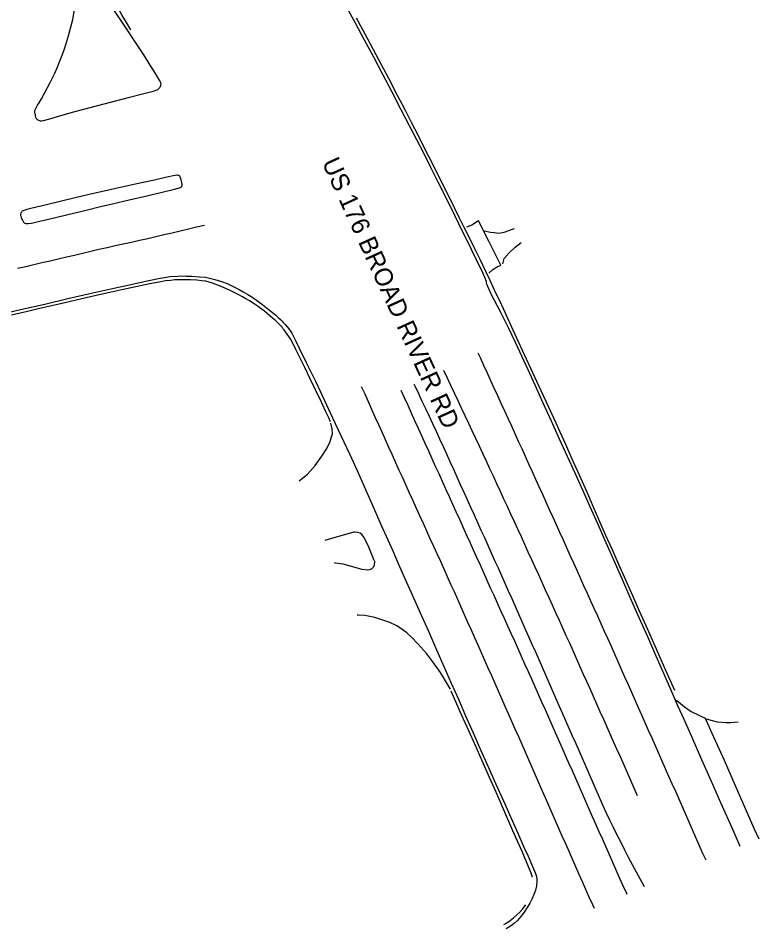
# Model space of a CAD drawing. Extents: x 1970211 to 1973046, y 801032 to 804001.
# Drawn here: x 1972824 to 1973045.8, y 801032.5 to 801305.3 of the extents above; entities that cross this region are included whole.
import ezdxf

# ---------------------------------------------------------------- set-up
doc = ezdxf.new("R2010")
doc.units = 0
for name, color, linetype in [('RD_EX_Conc', 7, 'Continuous'), ('RD_EX_Road', 7, 'Continuous'), ('RD_EX_Road_Paint', 7, 'Continuous'), ('RD_TX_RoadID', 7, 'Continuous')]:
    doc.layers.add(name, color=color, linetype=linetype)

msp = doc.modelspace()

# ---------------------------------------------------------------- linework, layer by layer
at = {"layer": 'RD_EX_Conc'}
for points in [[(1972851.73, 801309.15), (1972855.08, 801304.1), (1972859.53, 801297.36), (1972861.33, 801294.61), (1972862.52, 801292.76), (1972863.49, 801291.24), (1972864.56, 801289.55), (1972865.7, 801287.75), (1972866.4, 801286.57), (1972866.56, 801286.25), (1972866.63, 801286.04), (1972866.68, 801285.83), (1972866.71, 801285.63), (1972866.71, 801285.43), (1972866.69, 801285.26), (1972866.66, 801285.09), (1972866.62, 801284.95), (1972866.56, 801284.83), (1972866.41, 801284.59), (1972866.2, 801284.3), (1972865.99, 801284.03), (1972865.8, 801283.83), (1972865.55, 801283.71), (1972864.07, 801283.29), (1972861.3, 801282.59), (1972857.37, 801281.58), (1972852.4, 801280.28), (1972846.95, 801278.85), (1972841.32, 801277.37), (1972836.75, 801276.07), (1972833.45, 801275.04), (1972831.5, 801274.52), (1972831.03, 801274.46), (1972830.74, 801274.48), (1972830.48, 801274.54), (1972830.24, 801274.63), (1972830.03, 801274.74), (1972829.85, 801274.87), (1972829.69, 801275.01), (1972829.57, 801275.14), (1972829.48, 801275.27), (1972829.42, 801275.4), (1972829.36, 801275.54), (1972829.32, 801275.7), (1972829.27, 801276.02), (1972829.21, 801276.33), (1972829.13, 801276.63), (1972829.06, 801276.91), (1972829.01, 801277.17), (1972829.01, 801277.31), (1972829.03, 801277.47), (1972829.12, 801277.82), (1972829.29, 801278.23), (1972829.54, 801278.7), (1972829.87, 801279.26), (1972830.31, 801279.99), (1972831.01, 801281.21), (1972831.96, 801282.9), (1972832.85, 801284.53), (1972833.63, 801286.01), (1972834.34, 801287.42), (1972834.98, 801288.81), (1972835.68, 801290.43), (1972836.45, 801292.29), (1972837.19, 801294.2), (1972837.89, 801296.13), (1972838.53, 801298.05), (1972839.12, 801300.01), (1972839.73, 801302.29), (1972840.36, 801304.92), (1972840.91, 801307.84)], [(1972925.23, 801305.44), (1972927.14, 801301.93), (1972929.44, 801297.66), (1972932.05, 801292.76), (1972934.89, 801287.37), (1972937.58, 801282.21), (1972939.78, 801277.98), (1972941.77, 801274.15), (1972943.81, 801270.17), (1972945.86, 801266.13), (1972947.88, 801262.1), (1972950.01, 801257.82), (1972952.4, 801253.05), (1972954.59, 801248.65), (1972956.14, 801245.51), (1972957.44, 801242.87), (1972958.87, 801240), (1972960.49, 801236.72), (1972962.36, 801232.88), (1972964.09, 801229.31), (1972965.24, 801226.81), (1972966.14, 801224.84), (1972967.1, 801222.83), (1972968.13, 801220.69), (1972969.26, 801218.32), (1972970.7, 801215.22), (1972972.68, 801210.9), (1972975, 801205.83), (1972977.44, 801200.5), (1972979.84, 801195.28), (1972982.02, 801190.58), (1972983.81, 801186.72), (1972985.05, 801184.04), (1972986.24, 801181.41), (1972987.91, 801177.71), (1972989.89, 801173.28), (1972992.03, 801168.46), (1972994.2, 801163.57), (1972996.24, 801158.92), (1972998.17, 801154.53), (1972999.97, 801150.46), (1973001.81, 801146.32), (1973003.83, 801141.75), (1973005.93, 801137.01), (1973008, 801132.34), (1973010.02, 801127.77), (1973011.99, 801123.36), (1973015.1, 801116.34), (1973017.53, 801110.83), (1973020.55, 801103.98)], [(1972964.96, 801228.88), (1972966.17, 801230.04), (1972967.52, 801230.85), (1972968.61, 801231.33), (1972965.09, 801238.28), (1972961.92, 801244.63), (1972959.86, 801243.35), (1972958.28, 801242.72)], [(1972917.54, 801184.34), (1972917.02, 801185.62), (1972916.12, 801187.58), (1972914.84, 801190.28), (1972913.17, 801193.79), (1972911.41, 801197.47), (1972909.88, 801200.65), (1972908.5, 801203.47), (1972907.22, 801206.07), (1972906.18, 801208.11), (1972905.55, 801209.25), (1972905.09, 801209.95), (1972904.59, 801210.66), (1972904.1, 801211.33), (1972903.67, 801211.92), (1972903.32, 801212.39), (1972903.07, 801212.72), (1972902.78, 801213.06), (1972902.29, 801213.56), (1972901.66, 801214.17), (1972900.97, 801214.8), (1972900.23, 801215.47), (1972899.43, 801216.17), (1972898.61, 801216.88), (1972897.77, 801217.55), (1972896.82, 801218.26), (1972895.65, 801219.09), (1972894.41, 801219.92), (1972893.28, 801220.62), (1972892.21, 801221.24), (1972891.18, 801221.8), (1972890.08, 801222.39), (1972888.76, 801223.09), (1972887.3, 801223.83), (1972885.77, 801224.52), (1972884.35, 801225.12), (1972883.23, 801225.58), (1972882.26, 801225.95), (1972881.28, 801226.26), (1972880.23, 801226.51), (1972879.03, 801226.68), (1972877.53, 801226.8), (1972875.6, 801226.88), (1972873.67, 801226.93), (1972872.18, 801226.93), (1972870.92, 801226.88), (1972869.62, 801226.78), (1972868.13, 801226.59), (1972866.26, 801226.28), (1972863.48, 801225.73), (1972859.28, 801224.85), (1972855.11, 801223.95), (1972852.42, 801223.36), (1972850.09, 801222.85), (1972847.03, 801222.16), (1972843.06, 801221.25), (1972838.03, 801220.07), (1972833.25, 801218.94), (1972830.07, 801218.2), (1972826.86, 801217.47), (1972822.03, 801216.35)], [(1972930.66, 801142.87), (1972928.8, 801147.29), (1972927.6, 801149.87), (1972927.03, 801150.51), (1972926.41, 801151), (1972925.71, 801151.26), (1972924.94, 801151.32), (1972924.41, 801151.3), (1972923.83, 801151.16), (1972917.82, 801149.41), (1972915.89, 801148.87)], [(1972930.66, 801142.87), (1972930.7, 801142.53), (1972930.68, 801141.45), (1972930.36, 801140.77), (1972929.93, 801140.37), (1972929.29, 801140.06), (1972928.76, 801139.98), (1972927.02, 801140.09), (1972923.88, 801141), (1972921.36, 801141.7), (1972919.04, 801142.08), (1972918.81, 801142.1)], [(1972978.09, 801047.97), (1972977.68, 801049.15), (1972976.68, 801051.54), (1972974.92, 801055.61), (1972972.22, 801061.83), (1972969.37, 801068.37), (1972967.16, 801073.38), (1972965.18, 801077.86), (1972962.99, 801082.79), (1972960.86, 801087.61), (1972959.02, 801091.76), (1972956.84, 801096.64), (1972953.69, 801103.64)], [(1973021.14, 801101.03), (1973023.63, 801099), (1973025.59, 801097.63), (1973027.89, 801096.47), (1973029.73, 801095.56), (1973031.76, 801091.1), (1973035.42, 801083.01), (1973039.74, 801073.17), (1973044.37, 801062.68), (1973045.83, 801059.46)], [(1972969.51, 801033.79), (1972970.38, 801034.28), (1972971.39, 801034.98), (1972972.42, 801035.8), (1972973.4, 801036.66), (1972974.22, 801037.46), (1972975.05, 801038.39), (1972976.04, 801039.65)]]:
    msp.add_lwpolyline(points, dxfattribs=at)
msp.add_lwpolyline([(1972852.24, 801249.71), (1972853.85, 801250.08), (1972857.25, 801250.87), (1972862.56, 801252.11), (1972867.12, 801253.18), (1972870.46, 801253.97), (1972872.3, 801254.45), (1972872.65, 801254.58), (1972872.79, 801254.67), (1972872.91, 801254.76), (1972873, 801254.86), (1972873.06, 801254.97), (1972873.14, 801255.19), (1972873.18, 801255.41), (1972873.18, 801255.56), (1972873.08, 801256.09), (1972872.88, 801256.86), (1972872.69, 801257.46), (1972872.53, 801257.83), (1972872.44, 801257.96), (1972872.35, 801258.06), (1972872.25, 801258.13), (1972872.14, 801258.18), (1972872.01, 801258.22), (1972871.71, 801258.27), (1972871.52, 801258.28), (1972871.07, 801258.23), (1972870.47, 801258.11), (1972869.58, 801257.9), (1972868.16, 801257.57), (1972864.85, 801256.83), (1972859.54, 801255.66), (1972852.91, 801254.17), (1972845.32, 801252.45), (1972838.24, 801250.8), (1972832.12, 801249.35), (1972828.27, 801248.43), (1972826.67, 801248.04), (1972825.77, 801247.74), (1972825.49, 801247.6), (1972825.28, 801247.46), (1972825.11, 801247.29), (1972824.96, 801247.1), (1972824.85, 801246.89), (1972824.78, 801246.67), (1972824.75, 801246.45), (1972824.75, 801246.23), (1972824.8, 801246.01), (1972824.95, 801245.56), (1972825.14, 801245.07), (1972825.38, 801244.6), (1972825.67, 801244.2), (1972825.84, 801244.04), (1972826.06, 801243.91), (1972826.32, 801243.83), (1972826.61, 801243.78), (1972826.98, 801243.78), (1972827.98, 801243.92), (1972829.58, 801244.29), (1972833.12, 801245.13), (1972838.54, 801246.43), (1972844.04, 801247.75), (1972849.08, 801248.96)], close=True, dxfattribs=at)
at = {"layer": 'RD_EX_Road'}
for points in [[(1973040.29, 801057.1), (1973038.11, 801062), (1973034.47, 801070.23), (1973031.65, 801076.66), (1973028.8, 801083.16), (1973025.9, 801089.79), (1973023.51, 801095.16), (1973021.61, 801099.34), (1973019.45, 801104.21), (1973016.97, 801109.86), (1973014.68, 801115.1), (1973012.57, 801119.94), (1973010.12, 801125.5), (1973007.33, 801131.78), (1973004.78, 801137.56), (1973002.5, 801142.76), (1973000.16, 801148.08), (1972997.72, 801153.58), (1972995.36, 801158.88), (1972993.1, 801163.94), (1972990.83, 801168.97), (1972988.54, 801174.03), (1972986.17, 801179.23), (1972983.73, 801184.58), (1972981.28, 801189.98), (1972978.87, 801195.32), (1972976.74, 801200.01), (1972974.89, 801204.06), (1972972.98, 801208.12), (1972970.93, 801212.36), (1972968.44, 801217.31), (1972965.71, 801222.62), (1972964.36, 801225.59), (1972964.3, 801226.03), (1972964.28, 801226.4), (1972963.3, 801228.8), (1972961.29, 801232.96), (1972959.8, 801236.02), (1972958.86, 801237.93), (1972957.24, 801241.24), (1972954.85, 801246.16), (1972952.33, 801251.25), (1972949.83, 801256.23), (1972947.54, 801260.76), (1972945.47, 801264.86), (1972943.38, 801268.91), (1972941.2, 801273.08), (1972938.74, 801277.83), (1972936.01, 801283.15), (1972933.26, 801288.43), (1972930.53, 801293.61), (1972927.77, 801298.77), (1972925.02, 801303.85), (1972922.58, 801308.35)], [(1972963.61, 801241.59), (1972965.52, 801241.26), (1972966.63, 801241.14), (1972968.02, 801240.96), (1972969.61, 801241.25), (1972972.06, 801242.13), (1972972.64, 801242.32)], [(1972969.13, 801231.69), (1972969.61, 801233.37), (1972971.07, 801234.97), (1972972.85, 801236.76), (1972974.62, 801238.09)], [(1972817.17, 801216.28), (1972824.76, 801218), (1972832.01, 801219.68), (1972838.92, 801221.29), (1972845.49, 801222.83), (1972851.79, 801224.27), (1972857.73, 801225.58), (1972862.67, 801226.65), (1972866.54, 801227.46), (1972869.56, 801227.92), (1972871.8, 801228.06), (1972873.34, 801228.09), (1972874.37, 801228.06), (1972876.02, 801227.98), (1972878.31, 801227.86), (1972880.11, 801227.69), (1972881.37, 801227.47), (1972882.95, 801227.06), (1972884.9, 801226.47), (1972886.62, 801225.82), (1972888.02, 801225.15), (1972889.2, 801224.55), (1972890.23, 801224.01), (1972891.44, 801223.36), (1972892.85, 801222.57), (1972894.3, 801221.64), (1972895.78, 801220.56), (1972897.3, 801219.42), (1972898.85, 801218.24), (1972900.15, 801217.19), (1972901.18, 801216.3), (1972901.99, 801215.58), (1972902.6, 801215.02), (1972903.06, 801214.56), (1972903.42, 801214.15), (1972903.97, 801213.55), (1972904.7, 801212.74), (1972905.36, 801211.89), (1972905.96, 801210.92), (1972906.86, 801209.19), (1972908.18, 801206.48), (1972910.3, 801202.13), (1972913.14, 801196.32), (1972915.8, 801190.75), (1972918.19, 801185.61), (1972920.66, 801180.3), (1972923.21, 801174.83), (1972925.53, 801169.77), (1972927.63, 801165.05), (1972930.03, 801159.62), (1972932.68, 801153.61), (1972934.73, 801148.98), (1972936.19, 801145.73), (1972937.85, 801141.98), (1972939.85, 801137.48), (1972942.05, 801132.52), (1972944.42, 801127.18), (1972946.87, 801121.66), (1972949.34, 801116.06), (1972951.64, 801110.87), (1972953.75, 801106.09), (1972955.87, 801101.25), (1972958.04, 801096.28), (1972960.3, 801091.16), (1972962.63, 801085.92), (1972964.9, 801080.79), (1972967.1, 801075.8), (1972969.33, 801070.79), (1972971.55, 801065.8), (1972973.64, 801061.11), (1972975.5, 801056.94), (1972976.73, 801054.21), (1972977.36, 801052.83), (1972978.08, 801051.17), (1972978.93, 801049.1), (1972979.21, 801048.18), (1972979.36, 801047.37), (1972979.39, 801046.67), (1972979.25, 801045.39), (1972978.95, 801044.1), (1972978.5, 801042.81), (1972977.93, 801041.52), (1972977.23, 801040.2), (1972976.46, 801038.83), (1972975.57, 801037.46), (1972974.57, 801036.15), (1972973.57, 801035.02), (1972972.71, 801034.17), (1972971.81, 801033.47), (1972970.71, 801032.79), (1972970.14, 801032.49)], [(1972908.16, 801166.74), (1972910.63, 801168.7), (1972913.02, 801171.31), (1972915.01, 801174.12), (1972916.31, 801176.08), (1972917.34, 801178.17), (1972918.15, 801180.88), (1972918.11, 801182.25), (1972917.69, 801184.01)], [(1972953.53, 801104.33), (1972950.52, 801109.27), (1972948.22, 801112.5), (1972946.39, 801114.85), (1972943.75, 801117.88), (1972941.8, 801119.89), (1972940.38, 801121.12), (1972939.34, 801121.96), (1972937.42, 801123.25), (1972935.36, 801124.21), (1972933.26, 801124.99), (1972930.85, 801125.71), (1972927.84, 801126.32), (1972926, 801126.48), (1972925.58, 801126.44)], [(1973039.68, 801094.39), (1973037.43, 801094.22), (1973036, 801094.19), (1973033.49, 801094.39), (1973031.95, 801094.78), (1973030.19, 801095.31)]]:
    msp.add_lwpolyline(points, dxfattribs=at)
at = {"layer": 'RD_EX_Road_Paint'}
for points in [[(1972857.77, 801301.84), (1972856.5, 801303.99), (1972855.22, 801306.14), (1972853.95, 801308.29), (1972852.67, 801310.44), (1972851.39, 801312.59), (1972850.12, 801314.74), (1972848.84, 801316.89), (1972847.56, 801319.04), (1972846.29, 801321.19), (1972845.01, 801323.34), (1972843.73, 801325.49), (1972842.46, 801327.64), (1972841.18, 801329.79), (1972839.91, 801331.94), (1972838.63, 801334.09), (1972837.42, 801336.27), (1972836.22, 801338.47), (1972835.03, 801340.66), (1972833.83, 801342.86), (1972832.64, 801345.06), (1972831.44, 801347.25), (1972830.25, 801349.45), (1972830, 801349.9)], [(1972879.87, 801243.24), (1972877.44, 801242.67), (1972875, 801242.1), (1972872.57, 801241.53), (1972870.14, 801240.96), (1972867.7, 801240.39), (1972865.27, 801239.82), (1972862.84, 801239.25), (1972860.4, 801238.69), (1972857.96, 801238.15), (1972855.52, 801237.61), (1972853.08, 801237.07), (1972850.64, 801236.52), (1972848.21, 801235.97), (1972845.77, 801235.4), (1972843.34, 801234.83), (1972840.9, 801234.27), (1972838.47, 801233.7), (1972836.03, 801233.14), (1972833.6, 801232.57), (1972831.16, 801232), (1972828.73, 801231.44), (1972826.3, 801230.87), (1972823.86, 801230.31)], [(1973030.02, 801053.01), (1973029.01, 801055.29), (1973028, 801057.58), (1973026.99, 801059.87), (1973025.98, 801062.15), (1973024.97, 801064.44), (1973023.96, 801066.73), (1973022.95, 801069.02), (1973021.95, 801071.3), (1973020.94, 801073.59), (1973019.93, 801075.88), (1973018.92, 801078.16), (1973017.91, 801080.45), (1973016.9, 801082.74), (1973015.88, 801085.02), (1973014.87, 801087.31), (1973013.86, 801089.59), (1973012.84, 801091.88), (1973011.83, 801094.16), (1973010.82, 801096.45), (1973009.81, 801098.73), (1973008.79, 801101.02), (1973007.78, 801103.31), (1973006.77, 801105.59), (1973005.76, 801107.88), (1973004.74, 801110.16), (1973003.73, 801112.45), (1973002.72, 801114.73), (1973001.7, 801117.02), (1973000.68, 801119.3), (1972999.65, 801121.58), (1972998.62, 801123.85), (1972997.59, 801126.13), (1972996.56, 801128.41), (1972995.54, 801130.69), (1972994.51, 801132.97), (1972993.48, 801135.25), (1972992.45, 801137.53), (1972991.42, 801139.8), (1972990.39, 801142.08), (1972989.37, 801144.36), (1972988.34, 801146.64), (1972987.31, 801148.92), (1972986.28, 801151.2), (1972985.25, 801153.48), (1972984.22, 801155.75), (1972983.19, 801158.03), (1972982.16, 801160.31), (1972981.13, 801162.58), (1972980.09, 801164.86), (1972979.06, 801167.14), (1972978.03, 801169.42), (1972977, 801171.69), (1972975.97, 801173.97), (1972974.94, 801176.25), (1972973.9, 801178.52), (1972972.87, 801180.8), (1972971.84, 801183.08), (1972970.8, 801185.35), (1972969.75, 801187.62), (1972968.71, 801189.89), (1972967.67, 801192.16), (1972966.62, 801194.44), (1972965.58, 801196.71), (1972964.54, 801198.98), (1972963.49, 801201.25), (1972962.45, 801203.52), (1972961.79, 801204.95)], [(1972951.43, 801199.86), (1972952.49, 801197.6), (1972953.55, 801195.33), (1972954.61, 801193.07), (1972955.67, 801190.81), (1972956.73, 801188.54), (1972957.79, 801186.28), (1972958.85, 801184.02), (1972959.91, 801181.75), (1972960.98, 801179.49), (1972962.04, 801177.22), (1972963.1, 801174.96), (1972964.15, 801172.7), (1972965.2, 801170.43), (1972966.26, 801168.16), (1972967.31, 801165.89), (1972968.36, 801163.62), (1972969.41, 801161.35), (1972970.46, 801159.09), (1972971.51, 801156.82), (1972972.56, 801154.55), (1972973.61, 801152.28), (1972974.65, 801150.01), (1972975.68, 801147.73), (1972976.71, 801145.45), (1972977.75, 801143.18), (1972978.78, 801140.9), (1972979.81, 801138.62), (1972980.84, 801136.35), (1972981.88, 801134.07), (1972982.91, 801131.79), (1972983.94, 801129.52), (1972984.97, 801127.24), (1972986, 801124.96), (1972987.04, 801122.69), (1972988.07, 801120.41), (1972989.1, 801118.13), (1972990.13, 801115.85), (1972991.15, 801113.57), (1972992.17, 801111.29), (1972993.18, 801109), (1972994.2, 801106.72), (1972995.22, 801104.44), (1972996.23, 801102.15), (1972997.25, 801099.87), (1972998.27, 801097.58), (1972999.28, 801095.3), (1973000.3, 801093.02), (1973001.32, 801090.73), (1973002.33, 801088.45), (1973003.35, 801086.16), (1973004.37, 801083.88), (1973005.38, 801081.6), (1973006.4, 801079.31), (1973007.41, 801077.03), (1973008.43, 801074.74), (1973009.44, 801072.46)], [(1973011.6, 801045.08), (1973010.39, 801047.26), (1973009.19, 801049.45), (1973008.02, 801051.66), (1973006.85, 801053.87), (1973005.7, 801056.09), (1973004.57, 801058.32), (1973003.44, 801060.55), (1973002.34, 801062.8), (1973001.24, 801065.04), (1973000.15, 801067.29), (1972999.12, 801069.57), (1972998.11, 801071.86), (1972997.11, 801074.15), (1972996.1, 801076.43), (1972995.1, 801078.73), (1972994.1, 801081.02), (1972993.09, 801083.31), (1972992.09, 801085.6), (1972991.09, 801087.89), (1972990.09, 801090.18), (1972989.09, 801092.47), (1972988.09, 801094.76), (1972987.08, 801097.05), (1972986.07, 801099.33), (1972985.06, 801101.62), (1972984.06, 801103.91), (1972983.05, 801106.2), (1972982.04, 801108.49), (1972981.03, 801110.77), (1972980.02, 801113.06), (1972979.01, 801115.35), (1972978, 801117.64), (1972976.99, 801119.92), (1972975.98, 801122.21), (1972974.97, 801124.49), (1972973.96, 801126.78), (1972972.95, 801129.07), (1972971.93, 801131.35), (1972970.92, 801133.64), (1972969.91, 801135.92), (1972968.89, 801138.21), (1972967.86, 801140.49), (1972966.83, 801142.76), (1972965.8, 801145.04), (1972964.77, 801147.32), (1972963.74, 801149.6), (1972962.71, 801151.87), (1972961.68, 801154.15), (1972960.65, 801156.43), (1972959.62, 801158.71), (1972958.59, 801160.98), (1972957.56, 801163.26), (1972956.53, 801165.54), (1972955.5, 801167.82), (1972954.47, 801170.1), (1972953.44, 801172.37), (1972952.41, 801174.65), (1972951.38, 801176.93), (1972950.35, 801179.21), (1972949.3, 801181.47), (1972948.23, 801183.74), (1972947.17, 801186), (1972946.11, 801188.26), (1972945.04, 801190.52), (1972943.98, 801192.79), (1972942.92, 801195.05), (1972942.65, 801195.62)], [(1972926.78, 801195.02), (1972927.8, 801192.74), (1972928.83, 801190.46), (1972929.85, 801188.18), (1972930.88, 801185.9), (1972931.9, 801183.62), (1972932.93, 801181.34), (1972933.95, 801179.06), (1972934.98, 801176.78), (1972936, 801174.5), (1972937.03, 801172.22), (1972938.06, 801169.94), (1972939.09, 801167.67), (1972940.13, 801165.39), (1972941.16, 801163.11), (1972942.19, 801160.84), (1972943.22, 801158.56), (1972944.26, 801156.28), (1972945.29, 801154.01), (1972946.32, 801151.73), (1972947.36, 801149.45), (1972948.39, 801147.18), (1972949.42, 801144.9), (1972950.46, 801142.62), (1972951.49, 801140.35), (1972952.52, 801138.07), (1972953.55, 801135.79), (1972954.57, 801133.51), (1972955.59, 801131.23), (1972956.6, 801128.94), (1972957.62, 801126.66), (1972958.63, 801124.37), (1972959.65, 801122.09), (1972960.66, 801119.8), (1972961.68, 801117.52), (1972962.69, 801115.23), (1972963.71, 801112.95), (1972964.72, 801110.67), (1972965.74, 801108.38), (1972966.75, 801106.1), (1972967.77, 801103.81), (1972968.78, 801101.53), (1972969.8, 801099.24), (1972970.81, 801096.96), (1972971.81, 801094.67), (1972972.82, 801092.38), (1972973.82, 801090.09), (1972974.83, 801087.8), (1972975.83, 801085.51), (1972976.84, 801083.22), (1972977.84, 801080.93), (1972978.85, 801078.64), (1972979.85, 801076.35), (1972980.86, 801074.06), (1972981.86, 801071.78), (1972982.87, 801069.49), (1972983.87, 801067.2), (1972984.88, 801064.91), (1972985.88, 801062.62), (1972986.89, 801060.33), (1972987.9, 801058.05), (1972988.91, 801055.76), (1972989.93, 801053.47), (1972990.94, 801051.19), (1972991.95, 801048.9), (1972992.96, 801046.62), (1972993.97, 801044.33), (1972994.98, 801042.04), (1972996, 801039.76), (1972996.5, 801038.63)], [(1972938.64, 801193.91), (1972939.67, 801191.63), (1972940.7, 801189.36), (1972941.73, 801187.08), (1972942.76, 801184.8), (1972943.8, 801182.53), (1972944.83, 801180.25), (1972945.86, 801177.97), (1972946.89, 801175.7), (1972947.92, 801173.42), (1972948.96, 801171.14), (1972949.99, 801168.86), (1972951.02, 801166.59), (1972952.05, 801164.31), (1972953.08, 801162.03), (1972954.11, 801159.76), (1972955.15, 801157.48), (1972956.18, 801155.2), (1972957.2, 801152.92), (1972958.23, 801150.64), (1972959.26, 801148.36), (1972960.28, 801146.08), (1972961.31, 801143.8), (1972962.34, 801141.53), (1972963.36, 801139.25), (1972964.39, 801136.97), (1972965.42, 801134.69), (1972966.45, 801132.41), (1972967.48, 801130.13), (1972968.51, 801127.85), (1972969.54, 801125.58), (1972970.57, 801123.3), (1972971.6, 801121.02), (1972972.63, 801118.74), (1972973.66, 801116.46), (1972974.69, 801114.19), (1972975.71, 801111.91), (1972976.73, 801109.62), (1972977.75, 801107.34), (1972978.76, 801105.06), (1972979.78, 801102.77), (1972980.8, 801100.49), (1972981.81, 801098.2), (1972982.83, 801095.92), (1972983.85, 801093.64), (1972984.86, 801091.35), (1972985.87, 801089.06), (1972986.88, 801086.78), (1972987.88, 801084.49), (1972988.89, 801082.2), (1972989.9, 801079.91), (1972990.9, 801077.62), (1972991.91, 801075.33), (1972992.91, 801073.04), (1972993.92, 801070.75), (1972994.93, 801068.47), (1972995.94, 801066.18), (1972996.95, 801063.89), (1972997.96, 801061.61), (1972998.98, 801059.32), (1972999.99, 801057.04), (1973001, 801054.75), (1973002.01, 801052.47), (1973003.03, 801050.18), (1973004.04, 801047.9), (1973005.05, 801045.61), (1973006.07, 801043.33), (1973006.29, 801042.85)]]:
    msp.add_lwpolyline(points, dxfattribs=at)

# ---------------------------------------------------------------- texts
at = {"layer": 'RD_TX_RoadID'}
msp.add_text('US 176 BROAD RIVER RD', height=5.4, rotation=294.5447, dxfattribs=at).set_placement((1972914.91, 801262.07))

doc.saveas('drawing.dxf')
